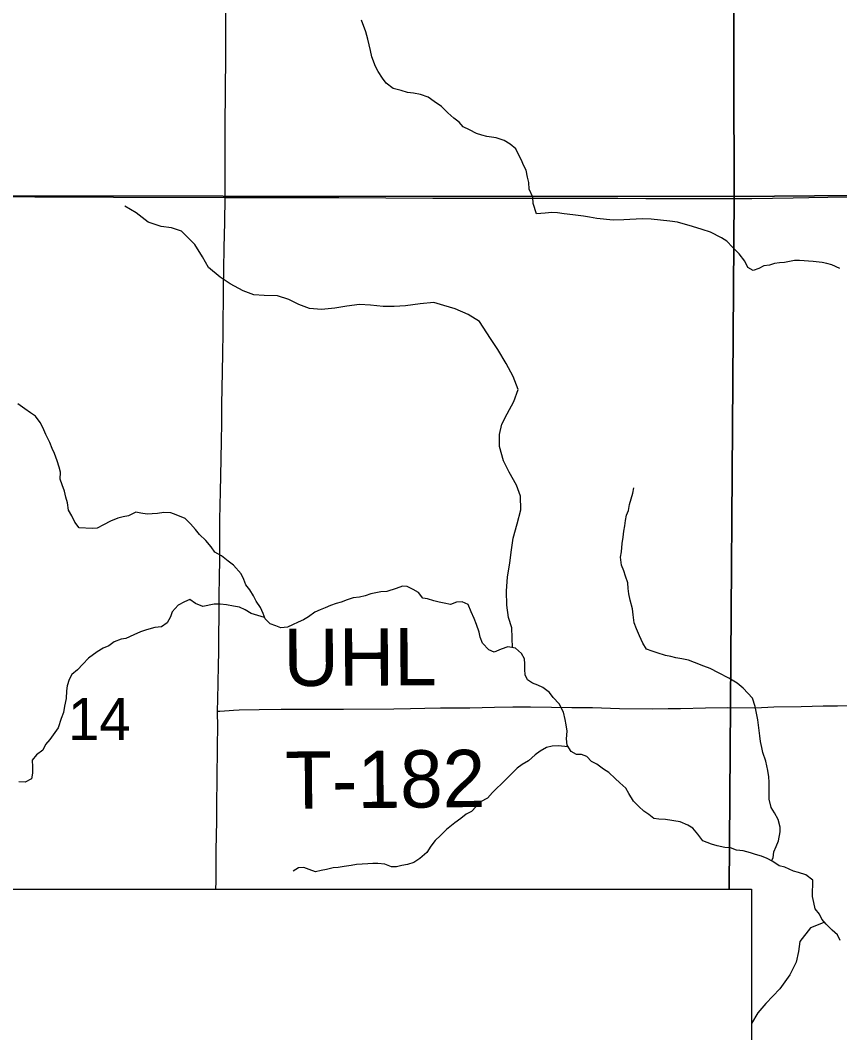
# Model space of a CAD drawing. Extents: x 0 to 34, y 0 to 22.
# Drawn here: x 3.95 to 4.762, y 19.089 to 20.093 of the extents above; entities that cross this region are included whole.
import ezdxf

# ---------------------------------------------------------------- set-up
doc = ezdxf.new("R2010")
doc.units = 0
for name, color, linetype in [('Default', 7, 'Continuous'), ('GM_X_County_Road', 7, 'Continuous'), ('GM_X_Minor_River', 7, 'Continuous'), ('GM_X_Section', 7, 'Continuous'), ('GM_X_Section_Text', 7, 'Continuous'), ('GM_X_Township_Road', 7, 'Continuous'), ('GM_X_Township_Road_Text', 7, 'Continuous'), ('SH_Text', 7, 'Continuous')]:
    doc.layers.add(name, color=color, linetype=linetype)

msp = doc.modelspace()

# ---------------------------------------------------------------- linework, layer by layer
at = {"layer": 'Default'}
for points in [[(4.655, 20.9), (3.6554, 20.9), (3.6434, 19.919), (4.6576, 19.9182)], [(5.6501, 20.9), (4.655, 20.9), (4.6576, 19.9182), (5.654, 19.9264)]]:
    msp.add_lwpolyline(points, close=True, dxfattribs=at)
at = {"layer": 'GM_X_County_Road'}
for points in [[(4.1527, 19.9174), (4.1527, 19.9328), (4.1528, 19.9514), (4.1527, 19.97), (4.1529, 19.9886), (4.1533, 20.057), (4.1533, 20.116), (4.1535, 20.1316), (4.1538, 20.1564), (4.1542, 20.1968), (4.1543, 20.2217), (4.1542, 20.2558), (4.1542, 20.2962), (4.1546, 20.3801), (4.1547, 20.4019), (4.1547, 20.4232)], [(3.6444, 19.9187), (3.6472, 19.9187), (3.6814, 19.9184), (3.7001, 19.9183), (3.7249, 19.9182), (3.7435, 19.918), (3.7715, 19.9177), (3.8026, 19.9179), (3.8585, 19.9179), (3.9207, 19.9181), (3.9393, 19.9181), (3.9642, 19.918), (4.0046, 19.9179), (4.0419, 19.9177), (4.1527, 19.9174)], [(4.1453, 19.4076), (4.1453, 19.4091), (4.1455, 19.4184), (4.1458, 19.4368), (4.1461, 19.4522), (4.1464, 19.4676), (4.1464, 19.4738), (4.1465, 19.48), (4.1469, 19.5049), (4.1469, 19.5241), (4.1472, 19.5387), (4.1475, 19.5594), (4.1476, 19.5979), (4.1481, 19.6256), (4.1485, 19.641), (4.1492, 19.6752), (4.1496, 19.6938), (4.1496, 19.7123), (4.1498, 19.7278), (4.1505, 19.762), (4.1507, 19.7837), (4.1513, 19.8272), (4.1515, 19.8458), (4.1519, 19.8676), (4.1524, 19.8924), (4.1527, 19.9174)], [(4.1527, 19.9174), (4.1537, 19.9174), (4.1786, 19.9171), (4.2283, 19.9173), (4.2655, 19.9171), (4.3121, 19.9168), (4.3588, 19.9165), (4.4116, 19.9167), (4.4489, 19.9167), (4.508, 19.9167), (4.5421, 19.9165), (4.5701, 19.9163), (4.5919, 19.9163), (4.6074, 19.9163), (4.6353, 19.9161), (4.6544, 19.9162), (4.6752, 19.9164), (4.7161, 19.9169), (4.7316, 19.9172), (4.7503, 19.9176), (4.8186, 19.9185)], [(4.1436, 19.2311), (4.1437, 19.2389), (4.1439, 19.2544), (4.144, 19.2684), (4.1443, 19.2854), (4.1444, 19.2978), (4.1446, 19.3174), (4.1449, 19.3381), (4.1452, 19.3743), (4.1454, 19.3917), (4.1453, 19.4076)]]:
    msp.add_lwpolyline(points, dxfattribs=at)
at = {"layer": 'GM_X_Minor_River'}
for points in [[(4.6626, 19.8614), (4.6558, 19.8679), (4.6504, 19.8739), (4.6451, 19.8773), (4.6341, 19.883), (4.6257, 19.8856), (4.6162, 19.8886), (4.6014, 19.8927), (4.5938, 19.8938), (4.5752, 19.8956), (4.5664, 19.896), (4.5482, 19.8951), (4.5376, 19.8947), (4.5213, 19.8965), (4.5141, 19.8976), (4.508, 19.8987), (4.4977, 19.9002), (4.489, 19.9009), (4.4822, 19.902), (4.4768, 19.9024), (4.47, 19.9016), (4.4617, 19.9012), (4.4582, 19.9114), (4.4578, 19.9175), (4.4543, 19.9255), (4.4539, 19.932), (4.4527, 19.9373), (4.4512, 19.9445), (4.4485, 19.9494), (4.4466, 19.9544), (4.4435, 19.9604), (4.4412, 19.9654), (4.4355, 19.9703), (4.4294, 19.9737), (4.4214, 19.9763), (4.4123, 19.9778), (4.4074, 19.9789), (4.402, 19.9808), (4.3952, 19.9842), (4.3887, 19.9872), (4.3849, 19.9921), (4.3796, 19.9959), (4.3735, 20.0012), (4.3674, 20.0076), (4.3601, 20.0125), (4.354, 20.0167), (4.3464, 20.0193), (4.3396, 20.0208), (4.3335, 20.0215), (4.3274, 20.0234), (4.3195, 20.0253), (4.3126, 20.0305), (4.3088, 20.0355), (4.3046, 20.0423), (4.3019, 20.0472), (4.2984, 20.0567), (4.2969, 20.0632), (4.2942, 20.0742), (4.2922, 20.0814), (4.288, 20.0932)], [(4.4378, 19.4707), (4.4372, 19.4904), (4.4338, 19.5007), (4.4322, 19.5128), (4.4317, 19.5268), (4.4328, 19.5409), (4.435, 19.5545), (4.4364, 19.5655), (4.4383, 19.5792), (4.4424, 19.5936), (4.4461, 19.6073), (4.4456, 19.621), (4.4418, 19.6319), (4.4345, 19.6448), (4.4288, 19.6561), (4.4249, 19.6701), (4.4248, 19.6823), (4.427, 19.6925), (4.4323, 19.7028), (4.439, 19.715), (4.4435, 19.7268), (4.4385, 19.7396), (4.4313, 19.7525), (4.4232, 19.7665), (4.416, 19.7774), (4.4049, 19.7941), (4.3939, 19.8012), (4.381, 19.8068), (4.3696, 19.8102), (4.3597, 19.8131), (4.3461, 19.8119), (4.3317, 19.8099), (4.3204, 19.8091), (4.3094, 19.8091), (4.2969, 19.8105), (4.2859, 19.8112), (4.2734, 19.8096), (4.2617, 19.8076), (4.2484, 19.806), (4.2363, 19.8071), (4.226, 19.8112), (4.2158, 19.8161), (4.2048, 19.8198), (4.1915, 19.8201), (4.1813, 19.8208), (4.1707, 19.8246), (4.1577, 19.8317), (4.1479, 19.8381), (4.1361, 19.8479), (4.1303, 19.8585), (4.1227, 19.8705), (4.1094, 19.8837), (4.0995, 19.8871), (4.0893, 19.8886), (4.0764, 19.8927), (4.0646, 19.9021), (4.0532, 19.9088)], [(4.7625, 19.8467), (4.7545, 19.8504), (4.7496, 19.8519), (4.7447, 19.8527), (4.7359, 19.8538), (4.7223, 19.8549), (4.7173, 19.8548), (4.7075, 19.8529), (4.7025, 19.8525), (4.6976, 19.8517), (4.6927, 19.8502), (4.687, 19.8494), (4.6821, 19.8467), (4.6764, 19.8448), (4.6711, 19.8478), (4.668, 19.8542), (4.6626, 19.8614)], [(4.3391, 19.5284), (4.3334, 19.5314), (4.3285, 19.5318), (4.3224, 19.5295), (4.313, 19.5264), (4.3073, 19.526), (4.3023, 19.5252), (4.2974, 19.524), (4.2917, 19.5221), (4.286, 19.5209), (4.2796, 19.5201), (4.2739, 19.5182), (4.2679, 19.5159), (4.2629, 19.5147), (4.2572, 19.5124), (4.2519, 19.5101), (4.247, 19.5082), (4.2417, 19.5059), (4.2353, 19.5013), (4.2304, 19.4982), (4.2251, 19.4959), (4.2194, 19.4933), (4.2145, 19.4909), (4.208, 19.4905), (4.2031, 19.4924), (4.1974, 19.4943), (4.1924, 19.4992), (4.1905, 19.5045), (4.1878, 19.5106), (4.1836, 19.5167), (4.1809, 19.522), (4.1771, 19.528), (4.1733, 19.533), (4.1713, 19.5383), (4.1687, 19.544), (4.161, 19.5527), (4.1557, 19.5565), (4.1492, 19.5617), (4.1424, 19.5655), (4.1389, 19.5708), (4.1336, 19.5769), (4.1275, 19.5829), (4.1233, 19.5879), (4.1183, 19.5935), (4.113, 19.5988), (4.1042, 19.6026), (4.0989, 19.6045), (4.0921, 19.6048), (4.0856, 19.6037), (4.0803, 19.6036), (4.0754, 19.6032), (4.0693, 19.6043), (4.0643, 19.6051), (4.0568, 19.6016), (4.0515, 19.6005), (4.0465, 19.5993), (4.039, 19.5962), (4.0322, 19.5924), (4.0257, 19.5893), (4.0208, 19.5889), (4.0079, 19.5896), (4.0037, 19.5953), (4.0006, 19.6014), (3.9975, 19.6071), (3.9964, 19.6143), (3.9948, 19.62), (3.9933, 19.6261), (3.9913, 19.6321), (3.989, 19.6378), (3.9894, 19.6447), (3.9882, 19.6496), (3.9863, 19.6561), (3.9836, 19.6633), (3.9813, 19.6682), (3.979, 19.6743), (3.9751, 19.6822), (3.9721, 19.6891), (3.9694, 19.694), (3.9648, 19.7004), (3.9598, 19.7038), (3.9541, 19.7076), (3.9473, 19.7125)], [(4.6946, 19.2592), (4.6961, 19.2624), (4.6969, 19.2681), (4.6991, 19.2734), (4.7014, 19.2791), (4.7032, 19.2879), (4.7032, 19.2928), (4.7012, 19.3004), (4.6974, 19.3069), (4.6944, 19.3122), (4.6924, 19.3205), (4.6923, 19.3372), (4.6919, 19.3426), (4.6911, 19.349), (4.6888, 19.3581), (4.6861, 19.3669), (4.6849, 19.3718), (4.6838, 19.3775), (4.683, 19.3832), (4.6822, 19.3885), (4.6818, 19.3938), (4.681, 19.3992), (4.6794, 19.4075), (4.6783, 19.4125), (4.6756, 19.4208), (4.6664, 19.4307), (4.6607, 19.4356), (4.6523, 19.4405), (4.642, 19.4458), (4.6337, 19.4499), (4.6276, 19.4525), (4.6181, 19.4559), (4.6124, 19.4582), (4.6055, 19.4597), (4.5998, 19.4608), (4.5949, 19.4619), (4.5896, 19.463), (4.5812, 19.4656), (4.5763, 19.4671), (4.5706, 19.4694), (4.5671, 19.4751), (4.5637, 19.4823), (4.5606, 19.4895), (4.5583, 19.4952), (4.5575, 19.5032), (4.5567, 19.5092), (4.5544, 19.518), (4.5532, 19.5241), (4.5524, 19.5294), (4.552, 19.5351), (4.5497, 19.5415), (4.5482, 19.5468), (4.5458, 19.5525), (4.545, 19.5605), (4.5458, 19.5658), (4.5465, 19.5742), (4.5476, 19.5803), (4.5483, 19.5864), (4.5491, 19.5917), (4.5498, 19.597), (4.5509, 19.602), (4.5528, 19.6069), (4.5539, 19.6127), (4.5554, 19.6184), (4.5572, 19.6241), (4.558, 19.6294)], [(4.7626, 19.1802), (4.7599, 19.1858), (4.7546, 19.1904), (4.7489, 19.1964), (4.7446, 19.2014), (4.7423, 19.2063), (4.7378, 19.2116), (4.7366, 19.2181), (4.7354, 19.2238), (4.7354, 19.2295), (4.7357, 19.2348), (4.7357, 19.2401), (4.7285, 19.2454), (4.7213, 19.2476), (4.7163, 19.2491), (4.7079, 19.2529), (4.7022, 19.2544), (4.6958, 19.2586), (4.6904, 19.2616), (4.6847, 19.2638), (4.6787, 19.2657), (4.6737, 19.2672), (4.6665, 19.2691), (4.66, 19.2698), (4.654, 19.2721), (4.6483, 19.2724), (4.6407, 19.2743), (4.635, 19.2758), (4.6266, 19.2792), (4.6216, 19.2856), (4.6167, 19.2917), (4.6117, 19.2947), (4.6041, 19.2981), (4.5893, 19.3003), (4.5828, 19.3006), (4.5779, 19.3014), (4.5729, 19.3051), (4.568, 19.3085), (4.563, 19.3131), (4.5577, 19.3184), (4.5531, 19.326), (4.55, 19.3313), (4.5443, 19.3366), (4.5394, 19.3411), (4.5333, 19.3468), (4.5279, 19.3502), (4.5215, 19.3551), (4.5161, 19.3577), (4.5115, 19.3627), (4.5062, 19.3649), (4.5013, 19.3649), (4.496, 19.3679), (4.4921, 19.374), (4.4913, 19.3804), (4.4921, 19.388), (4.4909, 19.3941), (4.4901, 19.3994), (4.4882, 19.4067), (4.4839, 19.415), (4.4782, 19.4214), (4.4744, 19.4264), (4.4679, 19.4313), (4.463, 19.4335), (4.4577, 19.4354), (4.4527, 19.4388), (4.4504, 19.4437), (4.45, 19.4491), (4.45, 19.4548), (4.4496, 19.4597), (4.4465, 19.465), (4.4408, 19.4703), (4.4332, 19.4714), (4.4264, 19.4691), (4.4195, 19.4664), (4.4142, 19.4687), (4.4081, 19.4751), (4.4058, 19.4812), (4.4046, 19.4861), (4.4019, 19.4937), (4.3996, 19.4998), (4.3969, 19.5062), (4.3939, 19.5134), (4.3878, 19.5161), (4.3821, 19.516), (4.3764, 19.5134), (4.3699, 19.5149), (4.365, 19.516), (4.3597, 19.5171), (4.3536, 19.519), (4.3487, 19.5197), (4.3445, 19.5254), (4.3391, 19.5284)], [(4.1917, 19.5007), (4.1787, 19.5045), (4.1726, 19.5082), (4.1669, 19.5109), (4.1609, 19.512), (4.154, 19.5131), (4.1479, 19.5138), (4.1419, 19.5138), (4.1305, 19.5115), (4.1233, 19.5145), (4.1179, 19.5186), (4.1126, 19.5163), (4.1062, 19.5129), (4.1002, 19.5064), (4.0987, 19.5014), (4.0953, 19.4953), (4.0896, 19.4915), (4.0832, 19.4907), (4.0748, 19.4884), (4.0688, 19.4865), (4.0623, 19.4834), (4.0544, 19.4799), (4.0495, 19.4792), (4.0426, 19.4765), (4.0373, 19.4726), (4.0317, 19.4703), (4.026, 19.4665), (4.0173, 19.4604), (4.0116, 19.4543), (4.0063, 19.4489), (4.0007, 19.444), (3.998, 19.439), (3.9962, 19.4329), (3.9954, 19.428), (3.9951, 19.4204), (3.9933, 19.4128), (3.9925, 19.4063), (3.9903, 19.4006), (3.9873, 19.3911), (3.979, 19.3796), (3.9745, 19.3746), (3.9719, 19.3689), (3.9658, 19.3643), (3.9613, 19.359), (3.9617, 19.3525), (3.9617, 19.3464), (3.9606, 19.3407), (3.9546, 19.3373), (3.9481, 19.3376)], [(4.493, 19.3725), (4.4929, 19.3725), (4.483, 19.3732), (4.477, 19.3731), (4.4713, 19.3716), (4.4652, 19.3681), (4.4603, 19.3643), (4.4535, 19.3586), (4.4474, 19.3548), (4.4425, 19.3513), (4.4308, 19.3395), (4.418, 19.3272), (4.4131, 19.3215), (4.4059, 19.3177), (4.3972, 19.3081), (4.3919, 19.3055), (4.3866, 19.3012), (4.3806, 19.297), (4.3723, 19.2905), (4.3662, 19.2844), (4.3609, 19.2795), (4.3568, 19.2737), (4.3527, 19.2676), (4.3459, 19.2615), (4.3398, 19.2577), (4.3337, 19.2558), (4.328, 19.2546), (4.3227, 19.2534), (4.3178, 19.2534), (4.311, 19.256), (4.3041, 19.2568), (4.2992, 19.2567), (4.2943, 19.2563), (4.2829, 19.2555), (4.2776, 19.2547), (4.2708, 19.2536), (4.2647, 19.2528), (4.2598, 19.2524), (4.2533, 19.2508), (4.248, 19.2497), (4.2423, 19.2485), (4.2362, 19.2508), (4.2309, 19.2526), (4.2256, 19.2522), (4.2203, 19.2492)], [(4.7471, 19.1985), (4.7441, 19.1971), (4.7332, 19.1929), (4.7226, 19.1792), (4.7212, 19.1693), (4.719, 19.1587), (4.7126, 19.1461), (4.7028, 19.1324), (4.6889, 19.1179), (4.681, 19.1084), (4.6746, 19.0978)]]:
    msp.add_lwpolyline(points, dxfattribs=at)
at = {"layer": 'GM_X_Section'}
for points in [[(4.6746, 18.9086), (5.6498, 18.8985), (5.6542, 19.8813), (5.654, 19.9264), (4.6576, 19.9182), (4.6526, 19.2311), (4.6746, 19.2311)], [(4.6526, 19.2311), (4.6576, 19.9182), (3.6434, 19.919), (3.6346, 19.2311)]]:
    msp.add_lwpolyline(points, close=True, dxfattribs=at)
at = {"layer": 'GM_X_Township_Road'}
msp.add_lwpolyline([(4.1453, 19.4076), (4.1475, 19.4078), (4.1522, 19.4081), (4.1569, 19.4084), (4.1611, 19.4086), (4.1667, 19.409), (4.1865, 19.4093), (4.2082, 19.4096), (4.2703, 19.4098), (4.3199, 19.4102), (4.3367, 19.4105), (4.3509, 19.4108), (4.3663, 19.4112), (4.3953, 19.4112), (4.4199, 19.4117), (4.4381, 19.412), (4.4555, 19.4119), (4.4764, 19.4118), (4.4967, 19.4115), (4.5172, 19.4113), (4.5438, 19.4105), (4.5765, 19.4102), (4.592, 19.4103), (4.6044, 19.4105), (4.6292, 19.4111), (4.6512, 19.4114), (4.6786, 19.4111), (4.6968, 19.4119), (4.7239, 19.4125), (4.7458, 19.413), (4.7601, 19.4131), (4.7776, 19.4135)], dxfattribs=at)
at = {"layer": 'SH_Text'}
msp.add_lwpolyline([(2.4548, 19.2311), (4.6746, 19.2311), (4.6746, 18.514), (2.4548, 18.514)], close=True, dxfattribs=at)

# ---------------------------------------------------------------- texts
at = {"layer": 'GM_X_Section_Text'}
msp.add_text('14', height=0.04186, rotation=0, dxfattribs=at).set_placement((3.9968, 19.379))
at = {"layer": 'GM_X_Township_Road_Text'}
for s, rotation, p in [('UHL', 0.337, (4.2108, 19.4326)), ('T-182', 0.5624, (4.2125, 19.3108))]:
    msp.add_text(s, height=0.05682, rotation=rotation, dxfattribs=at).set_placement(p)

doc.saveas('drawing.dxf')
